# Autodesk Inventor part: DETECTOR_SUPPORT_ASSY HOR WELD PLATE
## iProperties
Shininess: 64.0
Length Units: 11272
Angle Units: 11279
Time Units: 11290
Mass Units: 11286
Length Display Precision: 3
Angle Display Precision: 2
Compacted: True
Part Number: DETECTOR_SUPPORT_ASSY HOR WELD PLATE
Document SubType Name: Modeling
Created: 2004-08
Designer: John Blackburn
Material: MILD_STEEL
Manufacturer: Standard
Standards Organization: Custom
Density: 0.0
Volumn: 0.0
Area: 0.0
PropertySet Name: Model Information
Control State: 0
Master: False
Checked Out: False
Author: John Blackburn
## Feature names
1. ExtrusionMidplane1
2. ExtrusionThru1
3. ExtrusionMidThru1
